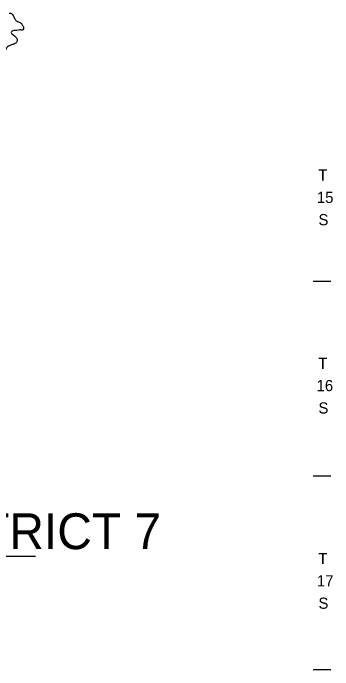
# Model space of a CAD drawing. Extents: x -17742 to 32032, y -17264 to 5867.
# Drawn here: x -14349 to -12630, y -11072 to -7541 of the extents above; entities that cross this region are included whole.
import ezdxf

# ---------------------------------------------------------------- set-up
doc = ezdxf.new("R2010")
doc.units = 0
for name, color, linetype in [('1', 7, 'Continuous'), ('2', 7, 'Continuous'), ('Default', 7, 'Continuous')]:
    doc.layers.add(name, color=color, linetype=linetype)

msp = doc.modelspace()

# ---------------------------------------------------------------- linework, layer by layer
at = {"layer": '1'}
msp.add_line((-17741.9, -10460.7), (-14228.8, -10460.7), dxfattribs=at)
msp.add_spline([(-14369, -7542.1), (-14362.9, -7541.6), (-14344.2, -7561.4), (-14336, -7577.9), (-14323.9, -7587.3), (-14310.1, -7592.2), (-14299.6, -7604.9), (-14292.5, -7618.6), (-14296.3, -7630.8), (-14311.7, -7631.9), (-14328.8, -7634.6), (-14345.3, -7634.1), (-14358.5, -7645.1), (-14346.4, -7659.9), (-14330.5, -7673.7), (-14326.1, -7688.5), (-14334.9, -7702.8), (-14352.5, -7710.6), (-14369.5, -7717.2), (-14384.9, -7730.4), (-14392.1, -7743), (-14409.2, -7748.5), (-14426.8, -7753.5), (-14442.2, -7755.1), (-14459.8, -7758.4), (-14476.9, -7766.7), (-14484, -7781), (-14481.8, -7801.4), (-14482.4, -7822.8), (-14464.2, -7830), (-14448.2, -7830.5), (-14432.8, -7838.8), (-14434.5, -7850.9), (-14446, -7866.3), (-14459.8, -7878.4), (-14473.5, -7884.5), (-14486.2, -7896), (-14481.8, -7907.6), (-14470.2, -7915.3), (-14462, -7927.9), (-14463.1, -7939.5), (-14476.3, -7947.8), (-14490.6, -7944.5), (-14501.1, -7930.7), (-14513.2, -7926.3), (-14523.6, -7921.3), (-14535.7, -7928.5), (-14535.7, -7944.5), (-14540.1, -7961.5), (-14536.3, -7974.2), (-14531.3, -7991.8), (-14531.9, -8005), (-14536.3, -8023.7), (-14545.6, -8043), (-14556.7, -8049), (-14561.1, -8028.1), (-14563.3, -8011), (-14569.9, -8001.1), (-14578.7, -8000.6), (-14590.2, -8008.8), (-14602.9, -8021.5), (-14618.8, -8035.3), (-14628.2, -8049), (-14623.2, -8066.1), (-14611.1, -8070.5), (-14601.8, -8067.2), (-14596.8, -8056.2), (-14587.5, -8054.5), (-14578.7, -8071.6)], degree=3, dxfattribs=at)
at = {"layer": 'Default'}
for p, q in [((-12641.6, -8983.8), (-12736.6, -8983.8)), ((-12641.6, -10030.9), (-12736.6, -10030.9)), ((-12641.6, -11071.5), (-12736.6, -11071.5))]:
    msp.add_line(p, q, dxfattribs=at)

# ---------------------------------------------------------------- texts
at = {"layer": '2'}
for s, height, p in [('T', 60, (-12708.7, -8441.8)), ('15', 60, (-12716.1, -8561.8)), ('S', 60, (-12707.6, -8681.8)), ('T', 60, (-12708.7, -9453.5)), ('16', 60, (-12717.7, -9573.5)), ('S', 60, (-12707.6, -9693.5)), ('ARKANSAS HIGHWAY DISTRICT 7', 192.623, (-17732.4, -10422.7)), ('T', 60, (-12708.7, -10503)), ('17', 60, (-12716.1, -10623)), ('S', 60, (-12707.6, -10743))]:
    msp.add_text(s, height=height, dxfattribs=at).set_placement(p)

doc.saveas('drawing.dxf')
